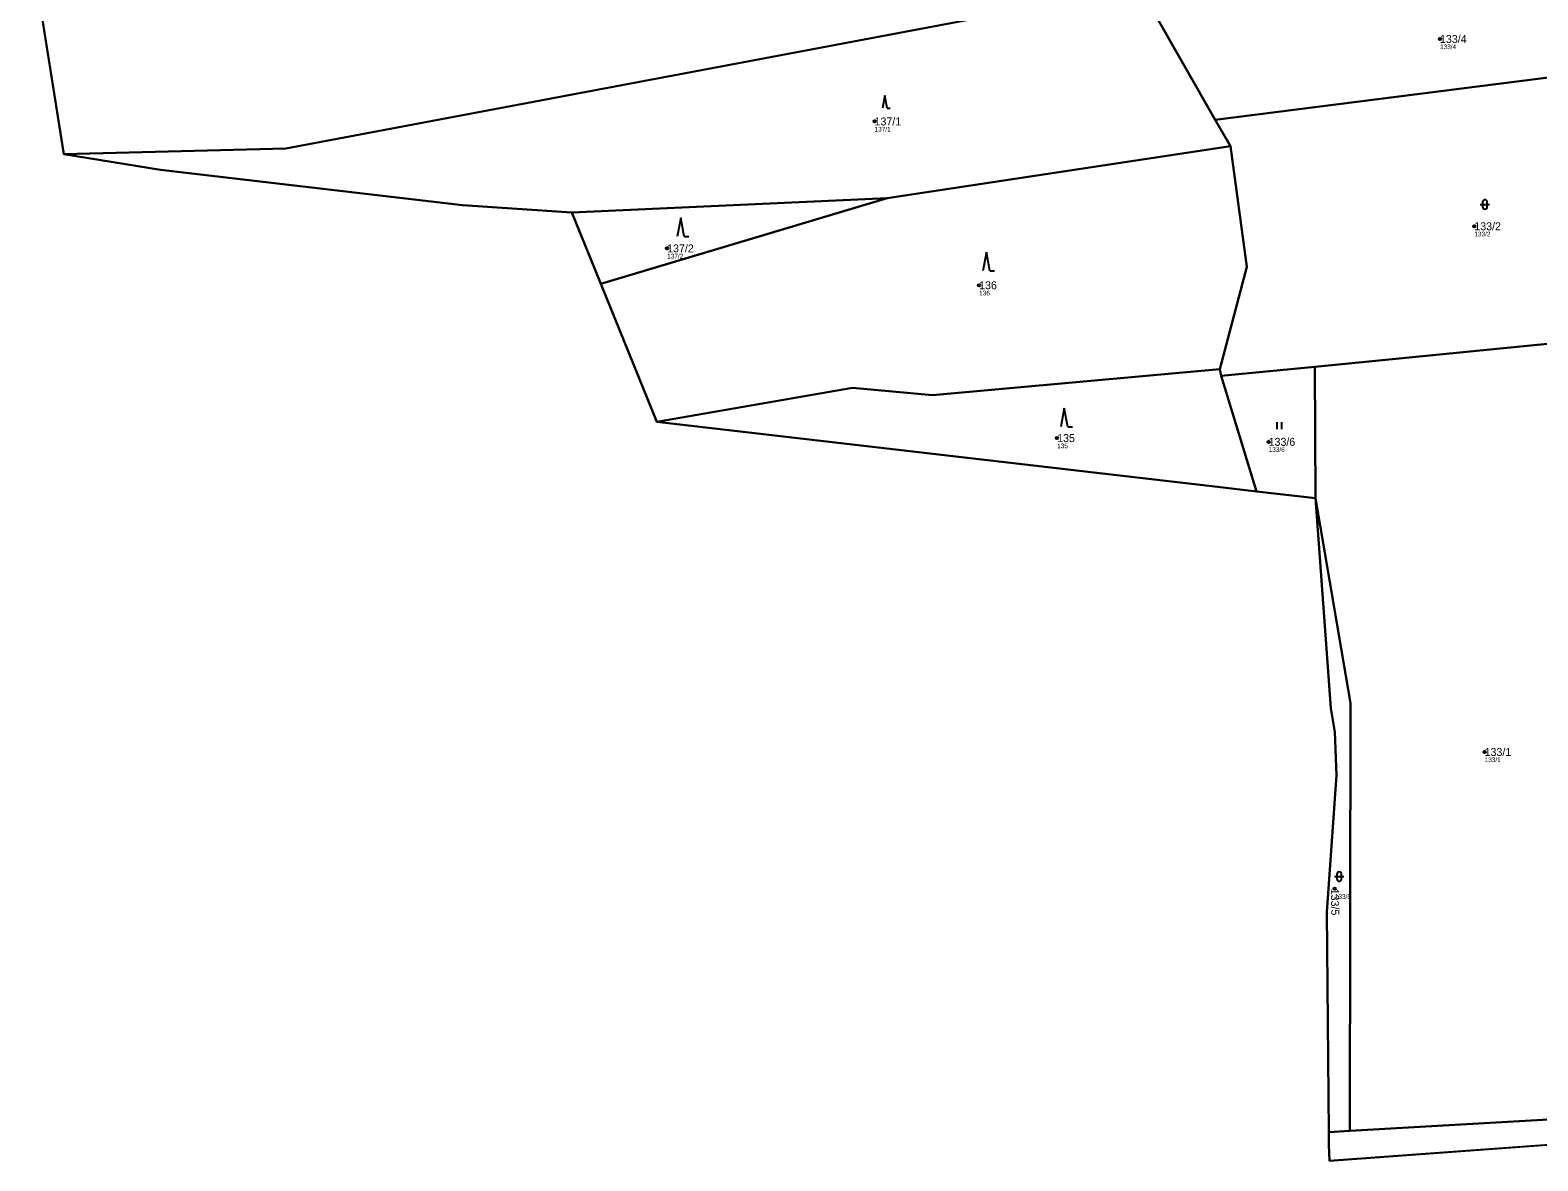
# Model space of a CAD drawing. Extents: x -767985 to -763816, y -1059600 to -1057360.
# Drawn here: x -766183.3 to -765861.4, y -1059532.8 to -1059291.5 of the extents above; entities that cross this region are included whole.
import ezdxf

# ---------------------------------------------------------------- set-up
doc = ezdxf.new("R2010")
doc.units = 0
for name, color, linetype in [('Definiční body', 7, 'Continuous'), ('Hranice parcel', 7, 'Continuous'), ('Parcelní čísla', 7, 'Continuous'), ('Polygon ku', 7, 'Continuous'), ('Polygon parcely', 7, 'Continuous'), ('Značky kultur', 7, 'Continuous')]:
    doc.layers.add(name, color=color, linetype=linetype)

msp = doc.modelspace()

# ---------------------------------------------------------------- linework, layer by layer
at = {"layer": 'Definiční body'}
for centre in [(-765882.28, -1059293.39994), (-766003, -1059310.99994), (-765874.95, -1059333.36994), (-766047.28, -1059338.08994), (-765980.67, -1059345.95994), (-765964.01, -1059378.57994), (-765918.87, -1059379.37994), (-765872.75, -1059445.56994), (-765904.73, -1059474.75994)]:
    msp.add_circle(centre, 0.25, dxfattribs=at)
at = {"layer": 'Hranice parcel'}
for p, q in [((-766176.07, -1059317.99), (-766183.27, -1059272.81)), ((-765943.82, -1059286.99), (-765930.24, -1059310.62)), ((-765821.58, -1059296.85), (-765930.24, -1059310.62)), ((-765930.24, -1059310.62), (-765926.99, -1059316.27)), ((-765926.99, -1059316.27), (-766000.3, -1059327.36)), ((-766155.47, -1059321.34), (-766176.07, -1059317.99)), ((-766090.98, -1059328.83), (-766155.47, -1059321.34)), ((-766067.63, -1059330.46), (-766090.98, -1059328.83)), ((-766067.63, -1059330.46), (-766000.3, -1059327.36)), ((-766000.3, -1059327.36), (-766061.42, -1059345.68)), ((-766064.08, -1059339.15), (-766067.63, -1059330.46)), ((-766063.57, -1059340.39), (-766064.08, -1059339.15)), ((-766061.42, -1059345.68), (-766063.57, -1059340.39)), ((-766049.45, -1059375.14), (-766061.42, -1059345.68)), ((-765929.27, -1059363.85), (-765928.97, -1059365.28)), ((-765928.97, -1059365.28), (-765909, -1059363.36)), ((-765928.97, -1059365.28), (-765921.45, -1059389.97)), ((-765909, -1059363.36), (-765908.85, -1059391.43)), ((-765929.81, -1059389), (-766049.45, -1059375.14)), ((-765921.45, -1059389.97), (-765929.81, -1059389)), ((-765908.85, -1059391.43), (-765921.45, -1059389.97)), ((-765905.61, -1059436.25), (-765908.85, -1059391.43)), ((-765901.54, -1059526.47), (-765835.4, -1059522.64)), ((-765906.04, -1059526.74), (-765901.54, -1059526.47)), ((-765906.02, -1059529.36), (-765906.04, -1059526.74)), ((-765905.89, -1059532.84), (-765906.02, -1059529.36)), ((-765847.8, -1059528.58), (-765905.89, -1059532.84))]:
    msp.add_line(p, q, dxfattribs=at)
for points in [[(-765968.23, -1059286.55), (-766128.68, -1059316.78), (-766176.07, -1059317.99)], [(-765926.99, -1059316.27), (-765923.52, -1059341.99), (-765929.27, -1059363.85)], [(-765839.22, -1059379.73), (-765838.46, -1059356.42), (-765909, -1059363.36)], [(-765929.27, -1059363.85), (-765990.62, -1059369.43), (-766007.7, -1059367.87), (-766049.45, -1059375.14)], [(-765908.85, -1059391.43), (-765901.36, -1059435.18), (-765901.54, -1059526.47)], [(-765904.39, -1059450.51), (-765904.74, -1059441.31), (-765905.61, -1059436.25)], [(-765906.04, -1059526.74), (-765906.43, -1059479.79), (-765904.39, -1059450.51)]]:
    msp.add_lwpolyline(points, dxfattribs=at)
at = {"layer": 'Polygon ku'}
msp.add_lwpolyline([(-766183.27, -1059272.81), (-766176.07, -1059317.99), (-766155.47, -1059321.34), (-766090.98, -1059328.83), (-766067.63, -1059330.46), (-766064.08, -1059339.15), (-766063.57, -1059340.39), (-766061.42, -1059345.68), (-766049.45, -1059375.14), (-765929.81, -1059389), (-765921.45, -1059389.97), (-765908.85, -1059391.43), (-765905.61, -1059436.25), (-765904.74, -1059441.31), (-765904.39, -1059450.51), (-765906.43, -1059479.79), (-765906.04, -1059526.74), (-765906.02, -1059529.36), (-765905.89, -1059532.84), (-765847.8, -1059528.58)], dxfattribs=at)
at = {"layer": 'Polygon parcely'}
for points in [[(-766183.27, -1059272.81), (-766176.07, -1059317.99), (-766128.68, -1059316.78), (-765968.23, -1059286.55), (-765971.08, -1059264.68), (-765972.01, -1059257.53), (-765992.33, -1059260.07), (-766009.78, -1059259.95), (-766008.89, -1059248.96), (-766084.73, -1059259.81)], [(-765930.24, -1059310.62), (-765821.58, -1059296.85), (-765831.62, -1059275.23), (-765833.57, -1059267.51), (-765875.06, -1059275.19), (-765943.82, -1059286.99)], [(-765967.62, -1059289.16), (-765968.23, -1059286.55), (-766128.68, -1059316.78), (-766176.07, -1059317.99), (-766155.47, -1059321.34), (-766090.98, -1059328.83), (-766067.63, -1059330.46), (-766000.3, -1059327.36), (-765926.99, -1059316.27), (-765930.24, -1059310.62), (-765943.82, -1059286.99), (-765946.02, -1059283.16)], [(-765923.52, -1059341.99), (-765929.27, -1059363.85), (-765928.97, -1059365.28), (-765909, -1059363.36), (-765838.46, -1059356.42), (-765839.22, -1059379.73), (-765811.49, -1059369.88), (-765804.78, -1059340.84), (-765821.58, -1059296.85), (-765930.24, -1059310.62), (-765926.99, -1059316.27)], [(-766061.42, -1059345.68), (-766049.45, -1059375.14), (-766007.7, -1059367.87), (-765990.62, -1059369.43), (-765929.27, -1059363.85), (-765923.52, -1059341.99), (-765926.99, -1059316.27), (-766000.3, -1059327.36)], [(-766064.08, -1059339.15), (-766063.57, -1059340.39), (-766061.42, -1059345.68), (-766000.3, -1059327.36), (-766067.63, -1059330.46)], [(-765908.85, -1059391.43), (-765901.36, -1059435.18), (-765901.54, -1059526.47), (-765835.4, -1059522.64), (-765839.27, -1059417.87), (-765840.41, -1059393.47), (-765839.22, -1059379.73), (-765838.46, -1059356.42), (-765909, -1059363.36)], [(-765990.62, -1059369.43), (-766007.7, -1059367.87), (-766049.45, -1059375.14), (-765929.81, -1059389), (-765921.45, -1059389.97), (-765928.97, -1059365.28), (-765929.27, -1059363.85)], [(-765928.97, -1059365.28), (-765921.45, -1059389.97), (-765908.85, -1059391.43), (-765909, -1059363.36)], [(-765901.54, -1059526.47), (-765901.36, -1059435.18), (-765908.85, -1059391.43), (-765905.61, -1059436.25), (-765904.74, -1059441.31), (-765904.39, -1059450.51), (-765906.43, -1059479.79), (-765906.04, -1059526.74)], [(-765906.04, -1059526.74), (-765906.02, -1059529.36), (-765905.89, -1059532.84), (-765847.8, -1059528.58), (-765840.31, -1059528.62), (-765818.27, -1059526.82), (-765786, -1059520.94), (-765762.68, -1059514.83), (-765749.83, -1059511.35), (-765724.61, -1059497.03), (-765725.5, -1059491.12), (-765728.23, -1059492.33), (-765750.04, -1059507.08), (-765788.23, -1059517.07), (-765824.17, -1059522.6), (-765830.22, -1059522.62), (-765835.4, -1059522.64), (-765901.54, -1059526.47)]]:
    msp.add_lwpolyline(points, close=True, dxfattribs=at)
at = {"layer": 'Značky kultur'}
for p, q in [((-766000.8, -1059305.46), (-766001.302, -1059308.14)), ((-766000.298, -1059308.14), (-766000.8, -1059305.46)), ((-766000.298, -1059308.14), (-765999.63, -1059308.14)), ((-765873.681, -1059328.701), (-765871.679, -1059328.701)), ((-765873.181, -1059328.201), (-765873.181, -1059329.202)), ((-765872.179, -1059329.202), (-765872.179, -1059328.201)), ((-766044.36, -1059331.55), (-766045.11, -1059335.55)), ((-766043.61, -1059335.55), (-766044.36, -1059331.55)), ((-766043.61, -1059335.55), (-766042.614, -1059335.55)), ((-765979.11, -1059338.87), (-765979.86, -1059342.87)), ((-765978.36, -1059342.87), (-765979.11, -1059338.87)), ((-765978.36, -1059342.87), (-765977.364, -1059342.87)), ((-765962.51, -1059372.18), (-765963.26, -1059376.18)), ((-765961.76, -1059376.18), (-765962.51, -1059372.18)), ((-765961.76, -1059376.18), (-765960.764, -1059376.18)), ((-765917.031, -1059376.68), (-765917.031, -1059375.18)), ((-765916.03, -1059376.68), (-765916.03, -1059375.18)), ((-765904.791, -1059472.181), (-765902.789, -1059472.181)), ((-765904.291, -1059471.681), (-765904.291, -1059472.682)), ((-765903.289, -1059472.682), (-765903.289, -1059471.681))]:
    msp.add_line(p, q, dxfattribs=at)
for centre, start, end in [((-765872.68, -1059328.2009), 0, 180), ((-765872.68, -1059329.2009), 180, 359.9878861), ((-765903.79, -1059471.6809), 0, 180), ((-765903.79, -1059472.6809), 180, 359.9878861)]:
    msp.add_arc(centre, 0.5, start, end, dxfattribs=at)

# ---------------------------------------------------------------- texts
at = {"layer": 'Definiční body'}
for s, p in [('133/4', (-765882.28, -1059295.556)), ('137/1', (-766003, -1059313.156)), ('133/2', (-765874.95, -1059335.526)), ('137/2', (-766047.28, -1059340.246)), ('136', (-765980.67, -1059348.116)), ('135', (-765964.01, -1059380.736)), ('133/6', (-765918.87, -1059381.536)), ('133/1', (-765872.75, -1059447.726)), ('133/5', (-765904.73, -1059476.916))]:
    msp.add_text(s, height=0.999996, dxfattribs=at).set_placement(p)
at = {"layer": 'Parcelní čísla'}
for s, p in [('133/4', (-765882.28, -1059294.25)), ('137/1', (-766003, -1059311.85)), ('133/2', (-765874.95, -1059334.22)), ('137/2', (-766047.28, -1059338.94)), ('136', (-765980.67, -1059346.81)), ('135', (-765964.01, -1059379.43)), ('133/6', (-765918.87, -1059380.23)), ('133/1', (-765872.75, -1059446.42))]:
    msp.add_text(s, height=1.699998, dxfattribs=at).set_placement(p)
msp.add_text('133/5', height=1.699998, rotation=271, dxfattribs=at).set_placement((-765905.579, -1059474.774))

doc.saveas('drawing.dxf')
